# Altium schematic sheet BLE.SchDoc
size A; DocumentNumber: 3; SheetNumber: 3; SheetTotal: 5
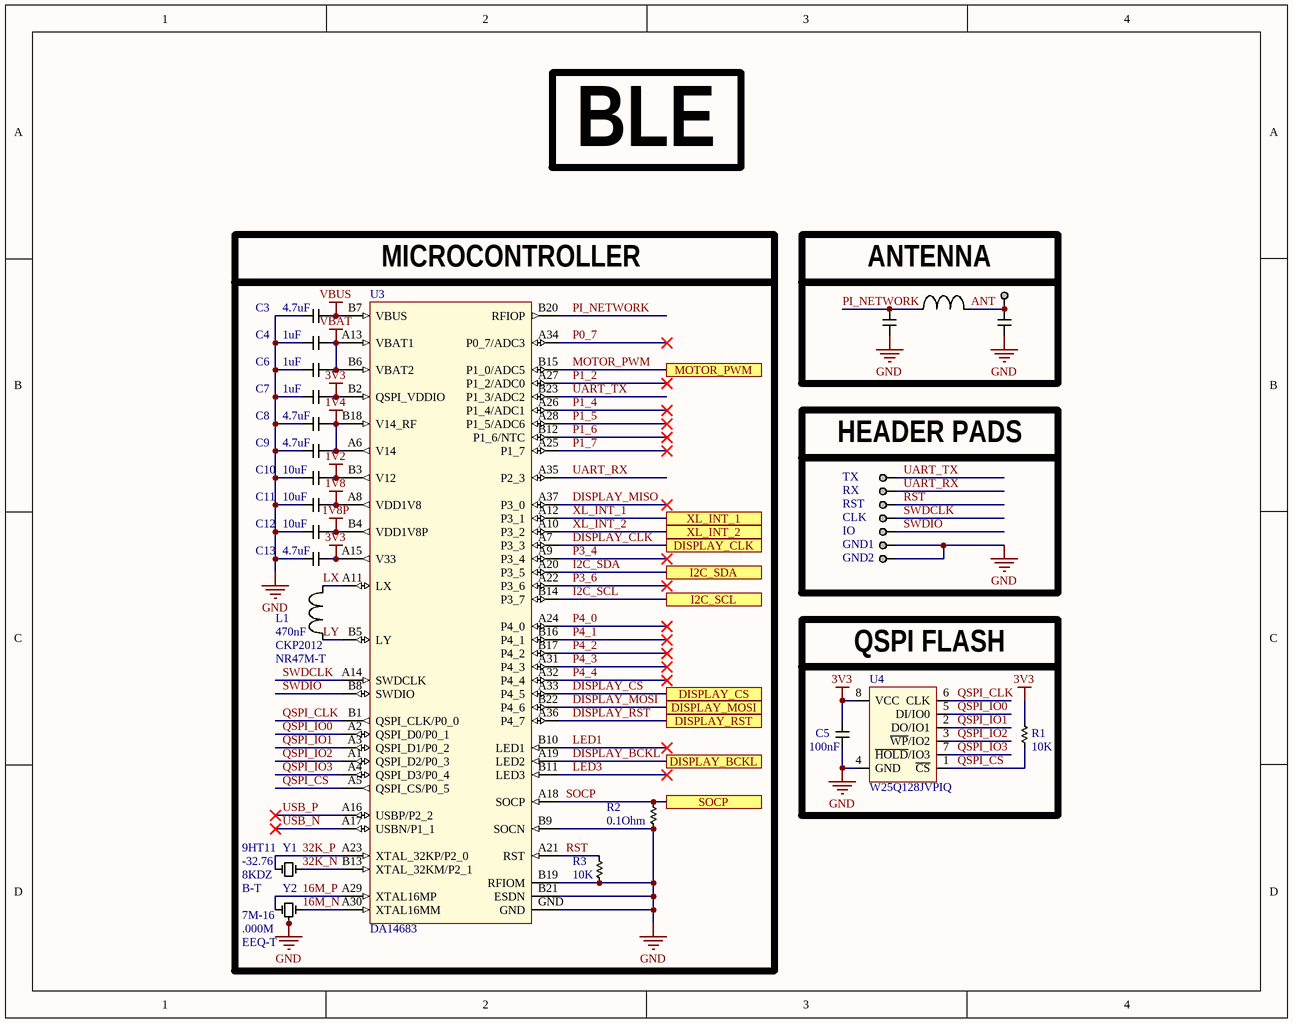
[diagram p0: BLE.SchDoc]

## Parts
ANT1  0.1" Header  [0.1" Header]  (value not drawn)  (no BOM)
C3  4.7uF  [CAP_0603_HIGH]
C4  1uF  [CAP_0603_HIGH]
C5  100nF  [CAP_0603_HIGH]
C6  1uF  [CAP_0603_HIGH]
C7  1uF  [CAP_0603_HIGH]
C8  4.7uF  [CAP_0603_HIGH]
C9  4.7uF  [CAP_0603_HIGH]
C10  10uF  [CAP_0603_HIGH]
C11  10uF  [CAP_0603_HIGH]
C12  10uF  [CAP_0603_HIGH]
C13  4.7uF  [CAP_0603_HIGH]
C16  C  [CAP_0402_MEDIUM]  (value not drawn)  (no BOM)
C17  C  [CAP_0402_MEDIUM]  (value not drawn)  (no BOM)
CLK  0.1" Pad  [0.1" Pad]  (value not drawn)  (no BOM)
GND1  0.1" Pad  [0.1" Pad]  (value not drawn)  (no BOM)
GND2  0.1" Pad  [0.1" Pad]  (value not drawn)  (no BOM)
IO  0.1" Pad  [0.1" Pad]  (value not drawn)  (no BOM)
L1  value 470nF  Parameter 1: CKP2012  Parameter 2: NR47M-T  [IND_0805_HIGH]  (hidden comment: CKP2012NR47M-T)
L2  L  [IND_0402_MEDIUM]  (value not drawn)  (no BOM)
R1  10K  [RES_0603_HIGH]
R2  0.1Ohm  [RES_0603_HIGH]
R3  10K  [RES_0603_HIGH]
RST  0.1" Pad  [0.1" Pad]  (value not drawn)  (no BOM)
RX  0.1" Pad  [0.1" Pad]  (value not drawn)  (no BOM)
TX  0.1" Pad  [0.1" Pad]  (value not drawn)  (no BOM)
U3  DA14683  [DA14683]
U4  W25Q128JVPIQ  [W25Q128JVPIQ]
Y1  Parameter 1: 9HT11  Parameter 2: -32.76  Parameter 3: 8KDZ  Parameter 4: B-T  [9HT11-32.768KDZB-T]  (hidden comment: 9HT11-32.768KDZB-T)
Y2  Parameter 1: 7M-16  Parameter 2: .000M  Parameter 3: EEQ-T  [7M-16.000MEEQ-T]  (hidden comment: 7M-16.000MEEQ-T)

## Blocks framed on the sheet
MICROCONTROLLER: C3 C4 C6-C13 L1 R2 R3 U3 Y1 Y2
ANTENNA: ANT1 C16 C17 L2
HEADER PADS: CLK GND1 GND2 IO RST RX TX
QSPI FLASH: C5 R1 U4

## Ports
DISPLAY_BCKL, DISPLAY_CLK, DISPLAY_CS, DISPLAY_MOSI, DISPLAY_RST, I2C_SCL, I2C_SDA, MOTOR_PWM, SOCP, XL_INT_1, XL_INT_2

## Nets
1V2: C10.1 U3.B3(V12)
1V4: C8.1 C9.1 U3.A6(V14) U3.B18(V14_RF)
1V8: C11.1 U3.A8(VDD1V8)
1V8P: C12.1 U3.B4(VDD1V8P)
3V3: C5.1 C7.1 C13.1 R1.2 U3.A15(V33) U3.B2(QSPI_VDDIO) U4.8(VCC)
GND: C3.2 C4.2 C5.2 C6.2 C7.2 C8.2 C9.2 C10.2 C11.2 C12.2 C13.2 C16.1 C17.1 GND1.1 GND2.1 R2.1 R3.1 U3.B9(SOCN) U3.B19(RFIOM) U3.B21(ESDN) U3.GND U4.4(GND) Y2.2 Y2.4
VBAT: C4.1 C6.1 U3.A13(VBAT1) U3.B6(VBAT2)
VBUS: C3.1 U3.B7(VBUS)
16M_N: U3.A30(XTAL16MM) Y2.3
16M_P: U3.A29(XTAL16MP) Y2.1
32K_N: U3.B13(XTAL_32KM/P2_1) Y1.2
32K_P: U3.A23(XTAL_32KP/P2_0) Y1.1
ANT: ANT1.1 C17.2 L2.1
DISPLAY_BCKL: U3.A19(LED2) ; port DISPLAY_BCKL
DISPLAY_CLK: U3.A7(P3_3) ; port DISPLAY_CLK
DISPLAY_CS: U3.A33(P4_5) ; port DISPLAY_CS
DISPLAY_MISO: U3.A37(P3_0)
DISPLAY_MOSI: U3.B22(P4_6) ; port DISPLAY_MOSI
DISPLAY_RST: U3.A36(P4_7) ; port DISPLAY_RST
I2C_SCL: U3.B14(P3_7) ; port I2C_SCL
I2C_SDA: U3.A20(P3_5) ; port I2C_SDA
LED1: U3.B10(LED1)
LED3: U3.B11(LED3)
LX: L1.2 U3.A11(LX)
LY: L1.1 U3.B5(LY)
MOTOR_PWM: U3.B15(P1_0/ADC5) ; port MOTOR_PWM
P0_7: U3.A34(P0_7/ADC3)
P1_2: U3.A27(P1_2/ADC0)
P1_4: U3.A26(P1_4/ADC1)
P1_5: U3.A28(P1_5/ADC6)
P1_6: U3.B12(P1_6/NTC)
P1_7: U3.A25(P1_7)
P3_4: U3.A9(P3_4)
P3_6: U3.A22(P3_6)
P4_0: U3.A24(P4_0)
P4_1: U3.B16(P4_1)
P4_2: U3.B17(P4_2)
P4_3: U3.A31(P4_3)
P4_4: U3.A32(P4_4)
PI_NETWORK: C16.2 L2.2 U3.B20(RFIOP)
QSPI_CLK: U3.B1(QSPI_CLK/P0_0) U4.6(CLK)
QSPI_CS: R1.1 U3.A5(QSPI_CS/P0_5) U4.1(~{CS})
QSPI_IO0: U3.A2(QSPI_D0/P0_1) U4.5(DI/IO0)
QSPI_IO1: U3.A3(QSPI_D1/P0_2) U4.2(DO/IO1)
QSPI_IO2: U3.A1(QSPI_D2/P0_3) U4.3(~{WP}/IO2)
QSPI_IO3: U3.A4(QSPI_D3/P0_4) U4.7(~{HOLD}/IO3)
RST: R3.2 RST.1 U3.A21(RST)
SOCP: R2.2 U3.A18(SOCP) ; port SOCP
SWDCLK: CLK.1 U3.A14(SWDCLK)
SWDIO: IO.1 U3.B8(SWDIO)
UART_RX: RX.1 U3.A35(P2_3)
UART_TX: TX.1 U3.B23(P1_3/ADC2)
USB_N: U3.A17(USBN/P1_1)
USB_P: U3.A16(USBP/P2_2)
XL_INT_1: U3.A12(P3_1) ; port XL_INT_1
XL_INT_2: U3.A10(P3_2) ; port XL_INT_2

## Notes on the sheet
- BLE

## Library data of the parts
C3-C13 = Capacitor_0603: 0603 Capacitor
C16 C17 = Capacitor_0402: 0402 Capacitor
L1 = Inductor_0805
L2 = Inductor_0402
R1-R3 = Resistor_0603: 0603 Resistor
U3 = DA14683: SmartBond DA14683 Single-chip high-security Bluetooth 5 solution with expandable memory
U4 = W25Q128JVPIQ: FLASH - NOR Memory IC 128Mb (16M x 8) SPI - Quad I/O, QPI, DTR 133MHz  8-WSON (6x5)
Y1 = 9HT11-32.768KDZB-T: 32.768kHz ±20ppm Crystal 6pF 90 kOhms 2-SMD, No Lead
Y2 = 7M-16.000MEEQ-T: 16MHz ±10ppm Crystal 10pF 80 Ohms 4-SMD, No Lead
